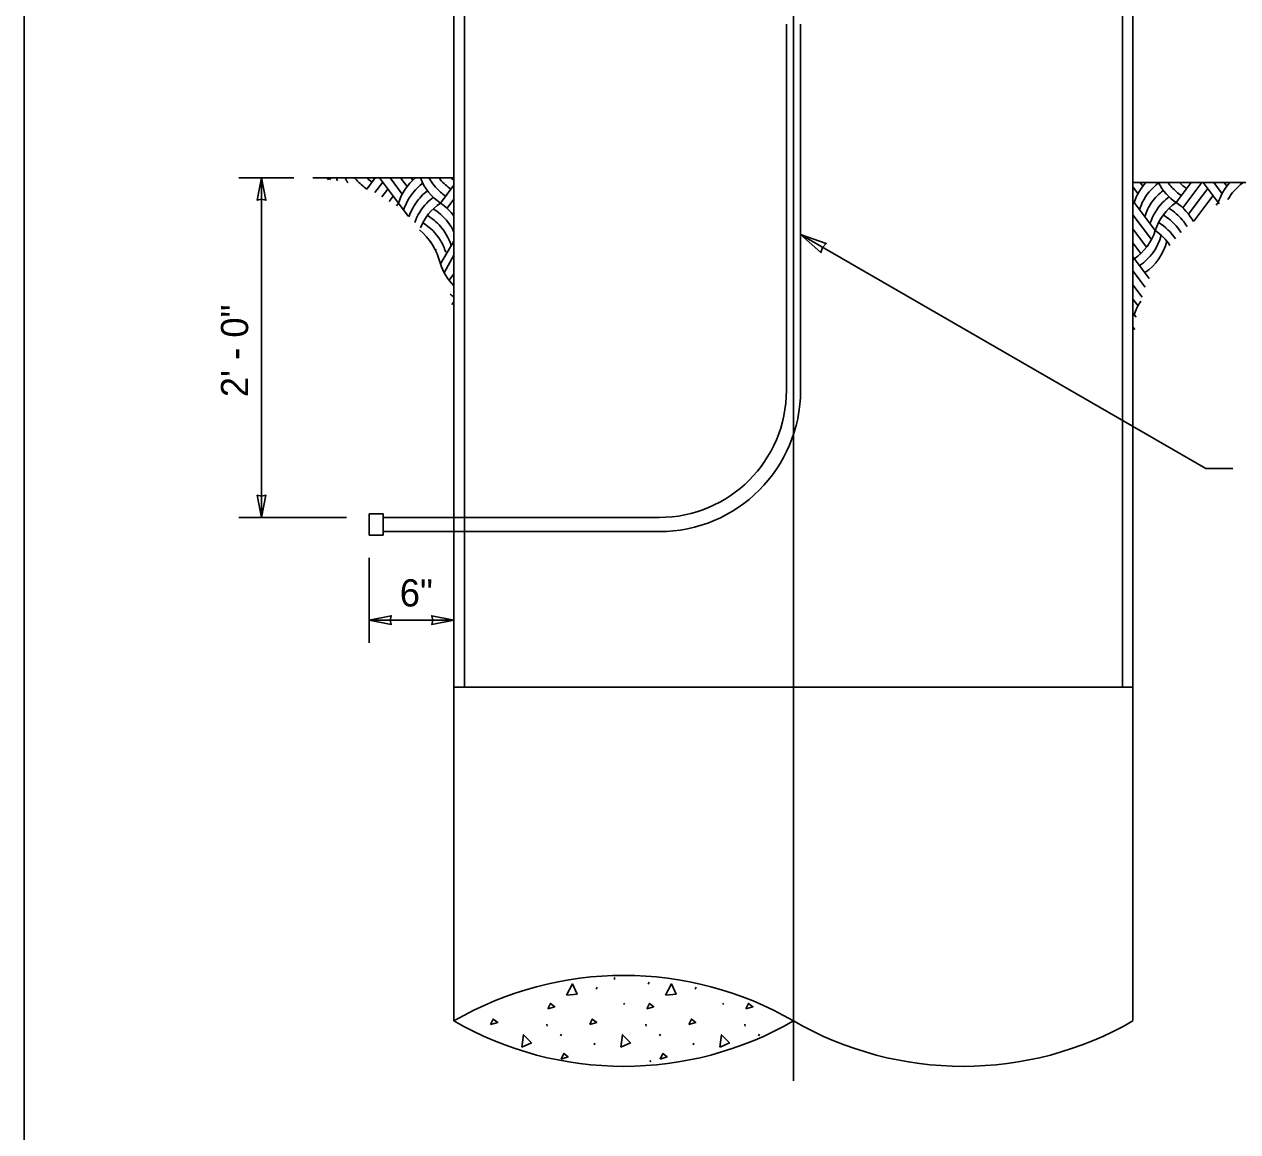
# Model space of a CAD drawing. Extents: x 99862 to 104211, y 98939 to 105076.
# Drawn here: x 100000 to 100714, y 101037 to 101689 of the extents above; entities that cross this region are included whole.
import ezdxf

# ---------------------------------------------------------------- set-up
doc = ezdxf.new("R2010")
doc.units = 0
for name, color, linetype in [('Level 10', 7, 'Continuous'), ('Level 15', 7, 'Continuous'), ('Level 2', 7, 'Continuous'), ('Level 20', 7, 'Continuous'), ('Level 6', 7, 'Continuous'), ('Level 60', 7, 'Continuous')]:
    doc.layers.add(name, color=color, linetype=linetype)

msp = doc.modelspace()

# ---------------------------------------------------------------- linework, layer by layer
at = {"layer": 'Level 10'}
for p, q in [((100346.89, 101126.78), (100347.41, 101127.95)), ((100367.06, 101124.08), (100367.58, 101125.25)), ((100336.42, 101121.11), (100336.93, 101122.27)), ((100394.66, 101121.11), (100395.18, 101122.27)), ((100352.58, 101112.83), (100353.1, 101112.06)), ((100410.82, 101112.83), (100411.34, 101112.06)), ((100307.41, 101100.43), (100307.54, 101099.27)), ((100315.47, 101093.57), (100315.99, 101094.73)), ((100365.65, 101100.43), (100365.78, 101099.27)), ((100373.71, 101093.57), (100374.23, 101094.73)), ((100423.9, 101100.43), (100424.03, 101099.27)), ((100431.96, 101093.57), (100432.48, 101094.73)), ((100335.12, 101088.27), (100335.64, 101089.43)), ((100393.37, 101088.27), (100393.89, 101089.43)), ((100368.04, 101079.09), (100368.56, 101078.31))]:
    msp.add_line(p, q, dxfattribs=at)
for points in [[(100318.96, 101117.62), (100322.45, 101124.21), (100325.17, 101118.14), (100319.09, 101117.62)], [(100377.21, 101117.62), (100380.7, 101124.21), (100383.41, 101118.14), (100377.33, 101117.62)], [(100307.91, 101109.47), (100309.46, 101112.7), (100312.05, 101110.76), (100307.91, 101109.47)], [(100366.16, 101109.47), (100367.71, 101112.7), (100370.29, 101110.76), (100366.16, 101109.47)], [(100424.4, 101109.47), (100425.95, 101112.7), (100428.54, 101110.76), (100424.4, 101109.47)], [(100274.32, 101100.23), (100275.87, 101103.46), (100278.46, 101101.52), (100274.32, 101100.23)], [(100332.56, 101100.23), (100334.12, 101103.46), (100336.7, 101101.52), (100332.56, 101100.23)], [(100390.81, 101100.23), (100392.36, 101103.46), (100394.94, 101101.52), (100390.81, 101100.23)], [(100292.61, 101086.93), (100293.64, 101094.32), (100298.27, 101089.53), (100292.73, 101086.97)], [(100350.85, 101086.93), (100351.88, 101094.32), (100356.51, 101089.53), (100350.98, 101086.97)], [(100409.1, 101086.93), (100410.13, 101094.32), (100414.76, 101089.53), (100409.22, 101086.97)], [(100315.73, 101079.99), (100317.28, 101083.22), (100319.87, 101081.28), (100315.73, 101079.99)], [(100373.97, 101079.99), (100375.52, 101083.22), (100378.11, 101081.28), (100373.97, 101079.99)]]:
    msp.add_lwpolyline(points, dxfattribs=at)
at = {"layer": 'Level 15'}
for p, q in [((100452.44, 101067.23), (100452.44, 101792.82)), ((100158.57, 101598.23), (100126.27, 101598.23)), ((100139.58, 101398.53), (100139.58, 101598.23)), ((100252.74, 101598.23), (100169.77, 101598.23)), ((100171.94, 101598.23), (100172.14, 101597.97)), ((100178.12, 101598.23), (100178.87, 101597.23)), ((100201.45, 101591.6), (100206.43, 101598.23)), ((100206.17, 101589.65), (100210.81, 101595.83)), ((100209.01, 101598.23), (100220.07, 101583.47)), ((100215.18, 101598.23), (100222.3, 101588.74)), ((100221.36, 101598.23), (100225.16, 101593.16)), ((100227.54, 101598.23), (100228.56, 101596.87)), ((100244.78, 101583.47), (100252.74, 101594.09)), ((100652.14, 101595.48), (100749.72, 101595.48)), ((100656.41, 101595.48), (100657.96, 101593.41)), ((100677.58, 101583.72), (100686.4, 101595.48)), ((100683.76, 101583.72), (100692.58, 101595.48)), ((100693.47, 101595.48), (100702.29, 101583.72)), ((100699.65, 101595.48), (100704.52, 101588.99)), ((100705.83, 101595.48), (100707.38, 101593.41)), ((100210.41, 101587.07), (100213.89, 101591.71)), ((100214.66, 101584.49), (100216.98, 101587.59)), ((100652.14, 101592.94), (100655.09, 101588.99)), ((100689.94, 101583.72), (100696.11, 101591.96)), ((100696.11, 101583.72), (100699.2, 101587.84)), ((100218.9, 101581.91), (100220.07, 101583.47)), ((100220.07, 101583.47), (100225.9, 101575.7)), ((100248.66, 101580.4), (100250.96, 101583.47)), ((100250.96, 101583.47), (100252.74, 101585.85)), ((100652.14, 101584.7), (100652.87, 101583.72)), ((100652.14, 101582.74), (100652.87, 101583.72)), ((100652.87, 101583.72), (100665.23, 101567.25)), ((100681.45, 101580.65), (100683.76, 101583.72)), ((100684.85, 101576.93), (100689.94, 101583.72)), ((100687.95, 101572.84), (100696.11, 101583.72)), ((100701.1, 101582.14), (100702.29, 101583.72)), ((100702.29, 101583.72), (100702.83, 101583)), ((100252.05, 101576.68), (100252.74, 101577.61)), ((100652.14, 101576.46), (100663, 101561.98)), ((100652.14, 101568.23), (100660.13, 101557.56)), ((100244.78, 101547.78), (100252.74, 101561.14)), ((100456.6, 101564.95), (100694.9, 101427.37)), ((100652.14, 101559.99), (100656.74, 101553.85)), ((100247.01, 101542.51), (100252.74, 101552.9)), ((100652.14, 101551.75), (100652.87, 101550.77)), ((100652.14, 101549.79), (100652.87, 101550.77)), ((100652.87, 101550.77), (100661.59, 101539.14)), ((100249.87, 101538.09), (100252.74, 101541.92)), ((100652.14, 101543.52), (100659.27, 101534)), ((100652.14, 101535.28), (100657.46, 101528.18)), ((100251.49, 101523.77), (100252.74, 101525.44)), ((100652.14, 101527.04), (100655.09, 101523.09)), ((100252.53, 101516.92), (100252.74, 101517.21)), ((100652.14, 101518.8), (100652.87, 101517.82)), ((100652.14, 101516.85), (100652.87, 101517.82)), ((100652.87, 101517.82), (100654, 101516.32)), ((100652.14, 101510.57), (100653.26, 101509.06)), ((100652.14, 101502.33), (100652.53, 101501.8)), ((100694.9, 101427.37), (100710.9, 101427.37)), ((100189.51, 101398.53), (100126.27, 101398.53)), ((100202.82, 101374.82), (100202.82, 101324.89)), ((100202.82, 101338.2), (100252.74, 101338.2))]:
    msp.add_line(p, q, dxfattribs=at)
for points in [[(100139.58, 101598.23), (100137.02, 101585.14), (100139.58, 101585.75), (100142.15, 101585.14)], [(100456.6, 101564.95), (100471.72, 101559.64), (100469.53, 101557.35), (100468.59, 101554.32)], [(100139.58, 101398.53), (100137.02, 101411.61), (100139.58, 101411.01), (100142.15, 101411.61)], [(100202.82, 101338.2), (100215.9, 101335.64), (100215.3, 101338.2), (100215.9, 101340.77)], [(100252.74, 101338.2), (100239.66, 101335.64), (100240.26, 101338.2), (100239.66, 101340.77)]]:
    msp.add_lwpolyline(points, close=True, dxfattribs=at)
for centre, start, end in [((100200.45, 101574), 129.20036, 132.18328), ((100212.8, 101609.42), 200.98531, 204.13986), ((100215.89, 101613.54), 209.33072, 215.62963), ((100218.98, 101617.66), 218.43096, 220.94161), ((100218.98, 101617.66), 220.94154, 236.09639), ((100222.07, 101621.78), 228.8764, 236.09639), ((100249.87, 101574), 129.20036, 162.3566), ((100252.96, 101569.88), 126.30625, 154.2266), ((100262.22, 101609.42), 200.98531, 236.09639), ((100265.31, 101613.54), 209.33072, 228.95992), ((100268.4, 101617.66), 218.43096, 220.94161), ((100268.4, 101617.66), 220.94154, 236.09639), ((100271.49, 101621.78), 228.8764, 233.16105), ((100682.67, 101574.24), 137.2229, 162.3566), ((100685.75, 101570.13), 126.30625, 154.2266), ((100695.02, 101609.67), 206.99554, 236.09639), ((100698.11, 101613.79), 215.84839, 228.95992), ((100701.2, 101617.91), 225.83725, 236.09639), ((100732.09, 101574.24), 137.2229, 162.3566), ((100735.18, 101570.13), 126.30625, 150.37482), ((100256.05, 101565.76), 127.1006, 145.49109), ((100265.31, 101613.54), 228.95986, 236.09639), ((100688.84, 101566.01), 127.1006, 145.49109), ((100691.93, 101561.89), 126.331, 135.71278), ((100698.11, 101613.79), 228.95986, 236.09639), ((100252.96, 101569.88), 154.22654, 162.3566), ((100256.05, 101565.76), 145.49102, 162.16441), ((100259.13, 101561.64), 135.71269, 160.47467), ((100262.22, 101557.52), 123.90361, 158.80712), ((100259.13, 101561.64), 126.331, 135.71278), ((100224.25, 101553.4), 48.95968, 58.54646), ((100227.34, 101557.52), 35.66892, 56.09634), ((100685.75, 101570.13), 154.22654, 162.3566), ((100688.84, 101566.01), 145.49102, 162.3566), ((100691.93, 101561.89), 135.71269, 162.3566), ((100695.02, 101557.77), 123.90361, 162.3566), ((100657.05, 101553.65), 48.95968, 58.54646), ((100660.14, 101557.77), 28.33702, 56.09634), ((100221.16, 101549.28), 40.94134, 59.30215), ((100224.25, 101553.4), 24.32954, 48.95975), ((100653.96, 101549.53), 40.94134, 59.30215), ((100657.05, 101553.65), 30.81393, 48.95975), ((100218.08, 101545.17), 31.33163, 58.48737), ((100221.16, 101549.28), 17.6434, 40.94141), ((100635.43, 101576.72), 303.90361, 342.3566), ((100647.78, 101541.3), 33.50474, 56.09639), ((100650.87, 101545.41), 32.90235, 58.48737), ((100653.96, 101549.53), 32.29688, 40.94141), ((100208.81, 101568.24), 344.91605, 346.31988), ((100218.08, 101545.17), 17.6434, 31.33172), ((100638.52, 101572.61), 303.90361, 345.01126), ((100641.61, 101568.49), 303.90361, 346.31988), ((100211.9, 101564.12), 344.22379, 345.77133), ((100214.99, 101557.25), 341.74698, 342.3566), ((100274.58, 101557.25), 197.64354, 225.70453), ((100271.49, 101553.14), 227.9507, 233.16105), ((100682.67, 101508.35), 146.08163, 162.3566)]:
    msp.add_arc(centre, 31.27, start, end, dxfattribs=at)
msp.add_ellipse((100214.99, 101536.3), major_axis=(0, 37.86), ratio=0.825772, start_param=5.020324, end_param=5.689011, dxfattribs=at)
at = {"layer": 'Level 2'}
for p, q in [((100252.74, 101698.08), (100252.74, 101298.69)), ((100258.98, 101698.08), (100258.98, 101298.69)), ((100645.89, 101698.08), (100645.89, 101298.69)), ((100652.14, 101698.08), (100652.14, 101298.69)), ((100252.74, 101102.45), (100252.74, 101298.69)), ((100252.74, 101298.69), (100258.98, 101298.69)), ((100258.98, 101298.69), (100645.89, 101298.69)), ((100645.89, 101298.69), (100258.98, 101298.69)), ((100645.89, 101298.69), (100652.14, 101298.69)), ((100652.14, 101298.69), (100652.14, 101298.69)), ((100652.14, 101102.75), (100652.14, 101298.69))]:
    msp.add_line(p, q, dxfattribs=at)
for centre, start, end in [((100352.59, 100929.51), 60, 120), ((100352.59, 101275.39), 240, 300), ((100552.29, 101275.39), 240, 300)]:
    msp.add_arc(centre, 199.7, start, end, dxfattribs=at)
at = {"layer": 'Level 6'}
for p, q in [((100448.28, 101688.64), (100448.28, 101473.42)), ((100456.6, 101688.64), (100456.6, 101473.42)), ((100202.82, 101388.13), (100202.82, 101400.61)), ((100211.14, 101400.61), (100202.82, 101400.61)), ((100211.14, 101388.13), (100211.14, 101400.61)), ((100252.74, 101398.53), (100211.14, 101398.53)), ((100252.74, 101398.53), (100373.39, 101398.53)), ((100202.82, 101388.13), (100211.14, 101388.13)), ((100211.14, 101390.21), (100252.74, 101390.21)), ((100252.74, 101390.21), (100373.39, 101390.21))]:
    msp.add_line(p, q, dxfattribs=at)
for radius in [83.21, 74.89]:
    msp.add_arc((100373.39, 101473.42), radius, 270, 0, dxfattribs=at)
at = {"layer": 'Level 60'}
msp.add_line((100000, 102075), (100000, 100000), dxfattribs=at)

# ---------------------------------------------------------------- texts
at = {"layer": 'Level 20'}
msp.add_text('2\' - 0"', height=16, rotation=90, dxfattribs=at).set_placement((100131.69, 101469.3))
msp.add_text('6"', height=16, dxfattribs=at).set_placement((100220.86, 101346.2))

doc.saveas('drawing.dxf')
